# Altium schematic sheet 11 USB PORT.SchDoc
size 420 x 297 mm
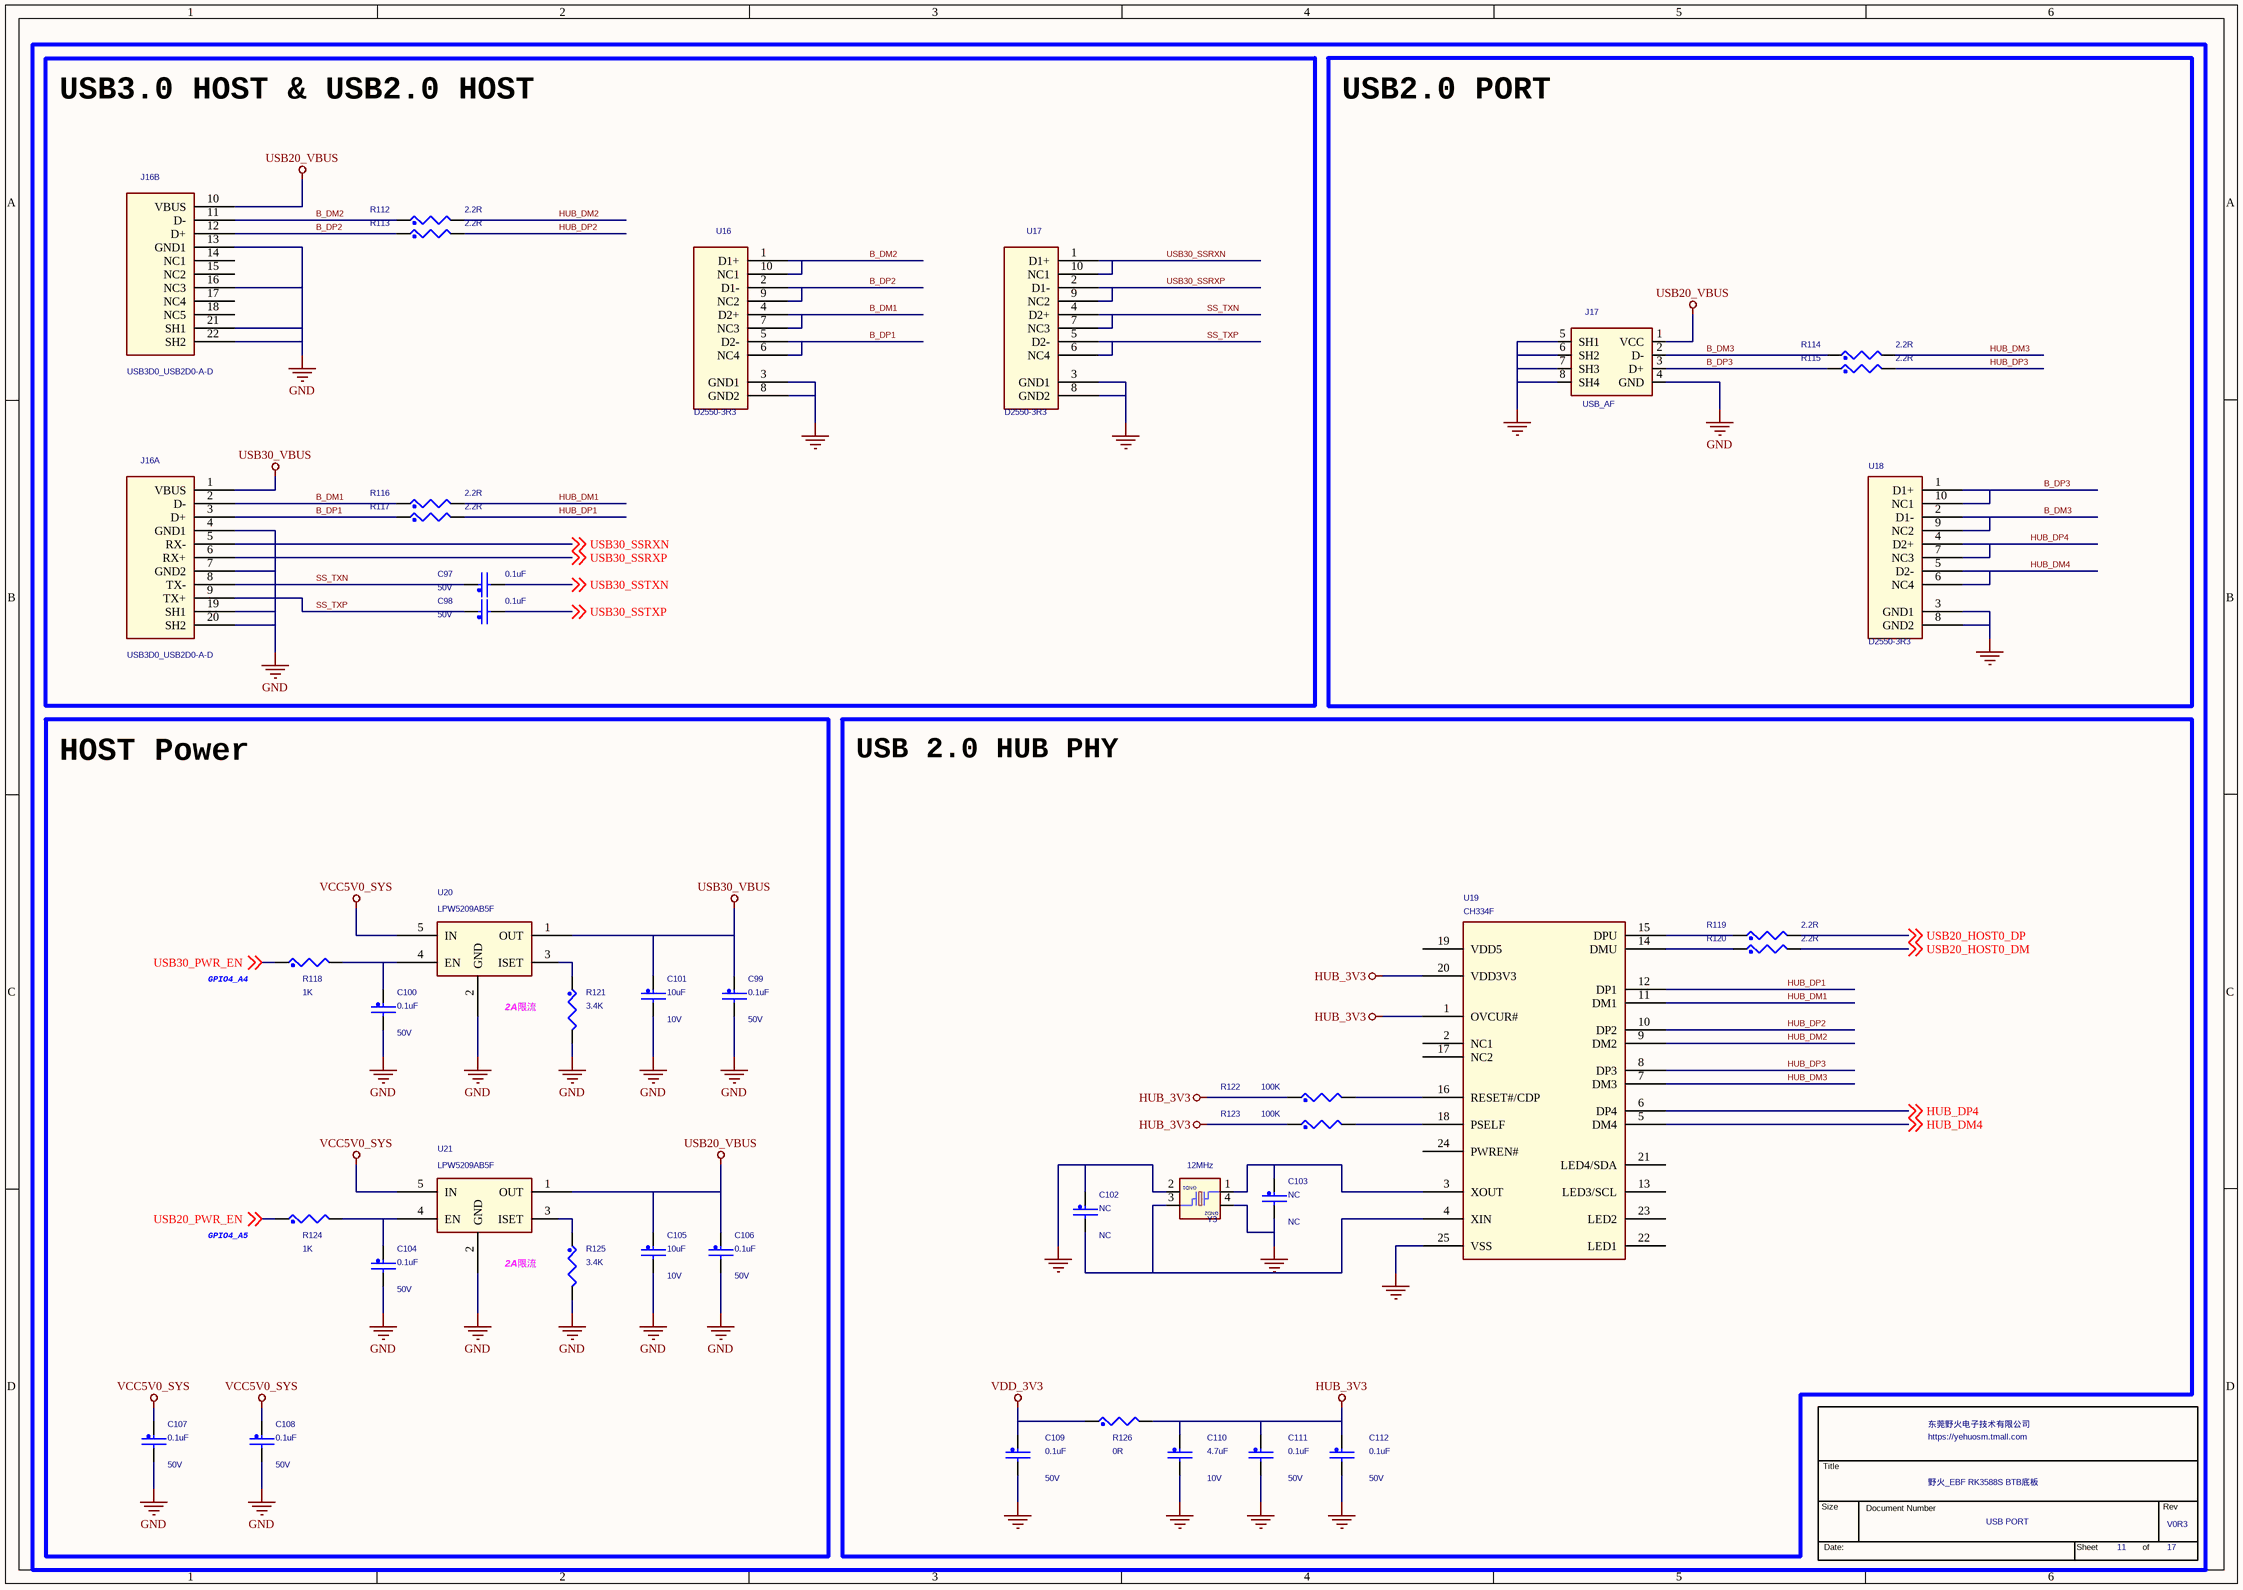
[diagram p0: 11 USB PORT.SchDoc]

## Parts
*  Page Count: 17  Page Number: 11  OrgName: 东莞野火电子技术有限公司  Title: 野火_EBF RK3588S BTB底板  RevCode: V0R3  Doc: USB PORT  (hidden comment: TitleBlock_YHSCH)  (graphical)
C97  0.1uF  Voltage: 50V  [C0402]
C98  0.1uF  Voltage: 50V  [C0402]
C99  0.1uF  Voltage: 50V  [C0402]
C100  0.1uF  Voltage: 50V  [C0402]
C101  10uF  Voltage: 10V  [C0402]
C102  NC  [C0402]
C103  NC  [C0402]
C104  0.1uF  Voltage: 50V  [C0402]
C105  10uF  Voltage: 10V  [C0402]
C106  0.1uF  Voltage: 50V  [C0402]
C107  0.1uF  Voltage: 50V  [C0402]
C108  0.1uF  Voltage: 50V  [C0402]
C109  0.1uF  Voltage: 50V  [C0402]
C110  4.7uF  Voltage: 10V  [C0402]
C111  0.1uF  Voltage: 50V  [C0402]
C112  0.1uF  Voltage: 50V  [C0402]
J16  USB3D0_USB2D0-A-D  [USB3D0-AF-18P]  (parts A,B of 2)
J17  USB_AF  [USB-AF]
R112  2.2R  [R0402]
R113  2.2R  [R0402]
R114  2.2R  [R0402]
R115  2.2R  [R0402]
R116  2.2R  [R0402]
R117  2.2R  [R0402]
R118  1K  [R0402]
R119  2.2R  [R0402]
R120  2.2R  [R0402]
R121  3.4K  [R0402]
R122  100K  [R0402]
R123  100K  [R0402]
R124  1K  [R0402]
R125  3.4K  [R0402]
R126  0R  [R0603]
U16  D2550-3R3  [son10_2r50x1r00x0r50]
U17  D2550-3R3  [son10_2r50x1r00x0r50]
U18  D2550-3R3  [son10_2r50x1r00x0r50]
U19  CH334F  [QFN24]
U20  LPW5209AB5F  [SOT23-5]
U21  LPW5209AB5F  [SOT23-5]
Y3  12MHz  [3225]

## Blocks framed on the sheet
USB3.0 HOST & USB2.0 HOST: C97 C98 J16 R112 R113 R116 R117 U16 U17
USB2.0 PORT: J17 R114 R115 U18
HOST Power: C99-C101 C104-C108 R118 R121 R124 R125 U20 U21
USB 2.0 HUB PHY: C102 C103 C109-C112 R119 R120 R122 R123 R126 U19 Y3

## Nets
GND: C99.2 C100.2 C101.2 C102.1 C103.2 C104.2 C105.2 C106.2 C107.2 C108.2 C109.2 C110.2 C111.2 C112.2 J16.4(GND1) J16.7(GND2) J16.13(GND1) J16.16(NC3) J16.19(SH1) J16.20(SH2) J16.21(SH1) J16.22(SH2) J17.4(GND) J17.5(SH1) J17.6(SH2) J17.7(SH3) J17.8(SH4) R121.2 R125.2 U16.3(GND1) U16.8(GND2) U17.3(GND1) U17.8(GND2) U18.3(GND1) U18.8(GND2) U19.25(VSS) U20.2(GND) U21.2(GND) Y3.2(GND1) Y3.4(GND2)
HUB_3V3: C110.1 C111.1 C112.1 R122.1 R123.1 R126.2 U19.1(OVCUR#) U19.20(VDD3V3)
USB20_VBUS: C105.1 C106.1 J16.10(VBUS) J17.1(VCC) U21.1(OUT)
USB30_VBUS: C99.1 C101.1 J16.1(VBUS) U20.1(OUT)
VCC5V0_SYS: C107.1 C108.1 U20.5(IN) U21.5(IN)
VDD_3V3: C109.1 R126.1
B_DM1: J16.2(D-) R116.1 U16.4(D2+) U16.7(NC3)
B_DM2: J16.11(D-) R112.1 U16.1(D1+) U16.10(NC1)
B_DM3: J17.2(D-) R114.1 U18.2(D1-) U18.9(NC2)
B_DP1: J16.3(D+) R117.1 U16.5(D2-) U16.6(NC4)
B_DP2: J16.12(D+) R113.1 U16.2(D1-) U16.9(NC2)
B_DP3: J17.3(D+) R115.1 U18.1(D1+) U18.10(NC1)
HUB_DM1: R116.2 U19.11(DM1)
HUB_DM2: R112.2 U19.9(DM2)
HUB_DM3: R114.2 U19.7(DM3)
HUB_DM4: U18.5(D2-) U18.6(NC4) U19.5(DM4) ; off-sheet HUB_DM4
HUB_DP1: R117.2 U19.12(DP1)
HUB_DP2: R113.2 U19.10(DP2)
HUB_DP3: R115.2 U19.8(DP3)
HUB_DP4: U18.4(D2+) U18.7(NC3) U19.6(DP4) ; off-sheet HUB_DP4
SS_TXN: C97.1 J16.8(TX-) U17.4(D2+) U17.7(NC3)
SS_TXP: C98.1 J16.9(TX+) U17.5(D2-) U17.6(NC4)
USB20_HOST0_DM: R120.2 ; off-sheet USB20_HOST0_DM
USB20_HOST0_DP: R119.2 ; off-sheet USB20_HOST0_DP
USB20_PWR_EN: R124.1 ; off-sheet USB20_PWR_EN
USB30_PWR_EN: R118.1 ; off-sheet USB30_PWR_EN
USB30_SSRXN: J16.5(RX-) U17.1(D1+) U17.10(NC1) ; off-sheet USB30_SSRXN
USB30_SSRXP: J16.6(RX+) U17.2(D1-) U17.9(NC2) ; off-sheet USB30_SSRXP
USB30_SSTXN: C97.2 ; off-sheet USB30_SSTXN
USB30_SSTXP: C98.2 ; off-sheet USB30_SSTXP
NetC100_1: C100.1 R118.2 U20.4(EN)
NetC102_2: C102.2 U19.4(XIN) Y3.3
NetC103_1: C103.1 U19.3(XOUT) Y3.1
NetC104_1: C104.1 R124.2 U21.4(EN)
NetR119_1: R119.1 U19.15(DPU)
NetR120_1: R120.1 U19.14(DMU)
NetR121_1: R121.1 U20.3(ISET)
NetR122_2: R122.2 U19.16(RESET#/CDP)
NetR123_2: R123.2 U19.18(PSELF)
NetR125_1: R125.1 U21.3(ISET)

Not connected (* = marked no-connect by the designer): J16 14(NC1) 15(NC2) 17(NC4) 18(NC5); U19 2(NC1) 13(LED3/SCL) 17(NC2) 19(VDD5) 21(LED4/SDA) 22(LED1) 23(LED2) 24(PWREN#)

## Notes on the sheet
- (near R118) GPIO4_A4
- (near U20) 2A限流
- (near R124) GPIO4_A5
- (near U21) 2A限流

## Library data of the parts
* = TitleBlock_YHSCH: Cage Code: 1
C97 C100 C104 C107 = CAP_NP: CLASS: DISCRETE; 生命周期: 量产; 价格: 0.029826; 规格书: 风华电容.pdf; 类别: 贴片电容0402; 品牌: 风华; 条码: EBF29060118; 规格编号: 0402X104K500NT; 规格: 贴片电容0.1uF 10% 50V X5R 0402
C98 C99 C106 C108 = CAP_NP: CLASS: DISCRETE; 规格: 贴片电容0.1uF 10% 50V X5R 0402; 规格编号: 0402X104K500NT; 条码: EBF29060118; 品牌: 风华; 类别: 贴片电容0402; 规格书: 风华电容.pdf; 价格: 0.029826; 生命周期: 量产
C101 C105 = CAP_NP: CLASS: DISCRETE; 规格: 贴片电容10uF 20% 10V X5R 0402; 规格编号: CL05A106MP8NUB8; 条码: EBF29060247; 品牌: 三星; 类别: 贴片电容0402; 规格书: 三星电容.pdf; 价格: 0.518415; 生命周期: 量产
C102 = CAP_NP: CLASS: DISCRETE; 类别: 贴片电容0402; 条码: EBF29060149; 规格: 贴片电容NC 预留
C103 = CAP_NP: CLASS: DISCRETE; 规格: 贴片电容NC 预留; 条码: EBF29060149; 类别: 贴片电容0402
C109 C111 C112 = CAP_NP: CLASS: DISCRETE; 规格: 贴片电容0.1uF 10% 50V X5R 0402; 规格编号: 0402X104K500NT; 条码: EBF29060118; 品牌: 风华; 类别: 贴片电容0402; 规格书: 风华电容.pdf; 生命周期: 量产; 价格: 0.029826
C110 = CAP_NP: CLASS: DISCRETE; 规格: 贴片电容4.7uF 10% 10V X5R 0402; 规格编号: CC0402KRX5R6BB475; 条码: EBF29060248; 品牌: 国巨; 类别: 贴片电容0402; 规格书: 国巨-贴片电容.pdf; 价格: 0.059058; 生命周期: 量产
J16 = USB3D0_USB2D0-A-D: 品牌: 富士康; 规格: USB3.0_USB2.0母座; 规格编号: UEA1112C-UHS6-4F; 条码: EBF29040092; 类别: USB接口; 规格书: UEA1112C-UHS6-4F.pdf; 生命周期: 量产
J17 = USB_AF: 生命周期: 量产; 价格: 0.5872; 规格书: 精拓金-USB侧插.pdf; 类别: USB接口; 品牌: 精拓金; 条码: EBF29040024; 规格编号: USB-AF侧插铜; 规格: 垂直 额定电流1.5A 母座 USB - Type A USB 2.0
R112 R115-R117 R119 = RES: CLASS: DISCRETE; 生命周期: 量产; 价格: 0.003072; 规格书: 厚声-无铅厚膜电阻.pdf; 类别: 贴片电阻0402; 品牌: 厚声; 条码: EBF29070280; 规格编号: 0402WGF220KTCE; 规格: 贴片电阻2.2R 1% 1/16W 0402
R113 R114 R120 = RES: CLASS: DISCRETE; 规格: 贴片电阻2.2R 1% 1/16W 0402; 规格编号: 0402WGF220KTCE; 条码: EBF29070280; 品牌: 厚声; 类别: 贴片电阻0402; 规格书: 厚声-无铅厚膜电阻.pdf; 价格: 0.003072; 生命周期: 量产
R118 R124 = RES: CLASS: DISCRETE; 生命周期: 量产; 规格书: 合科泰-RI系列电阻.pdf; 类别: 贴片电阻0402; 品牌: 合科泰; 条码: EBF29070050; 规格编号: RI0402L1001FT; 规格: 贴片电阻1K 1% 1/16W 0402
R121 = RES: CLASS: DISCRETE; 生命周期: 量产; 规格书: 合科泰-RI系列电阻.pdf; 类别: 贴片电阻0402; 品牌: 合科泰; 条码: EBF29070186; 规格编号: RI0402L3401FT; 规格: 贴片电阻3.4K 1% 1/16W 0402
R122 = RES: CLASS: DISCRETE; 生命周期: 量产; 规格书: 合科泰-RI系列电阻.pdf; 类别: 贴片电阻0402; 品牌: 合科泰; 条码: EBF29070054; 规格编号: RI0402L1003FT; 规格: 贴片电阻100K 1% 1/16W 0402
R123 = RES: CLASS: DISCRETE; 规格: 贴片电阻100K 1% 1/16W 0402; 规格编号: RI0402L1003FT; 条码: EBF29070054; 品牌: 合科泰; 类别: 贴片电阻0402; 规格书: 合科泰-RI系列电阻.pdf; 生命周期: 量产
R125 = RES: CLASS: DISCRETE; 规格: 贴片电阻3.4K 1% 1/16W 0402; 规格编号: RI0402L3401FT; 条码: EBF29070186; 品牌: 合科泰; 类别: 贴片电阻0402; 规格书: 合科泰-RI系列电阻.pdf; 生命周期: 量产
R126 = RES: CLASS: DISCRETE; 生命周期: 量产; 规格书: 合科泰-RI系列电阻.pdf; 类别: 贴片电阻0603; 品牌: 合科泰; 条码: EBF29070063; 规格编号: RI0603L0000FT; 规格: 贴片电阻0R 1% 1/10W 0603
U16 = RCLAMP0524P: 丝印: 3324P; 备注: 猫5 HDMI2.1新物料; 规格: 用于 USB3.0、HDMI2.1和高速接口的四路0.13pF、3.3V、±12kV ESD 保护二极管; 条码: EBFCIS231110170954; 品牌: 千虹; 类别: 贴片四路ESD; 规格书: 千虹_D2550-3R3.pdf; 生命周期: 量产
U17 U18 = RCLAMP0524P: 丝印: 3324P; 备注: 猫5 HDMI2.1新物料; 生命周期: 量产; 规格书: 千虹_D2550-3R3.pdf; 类别: 贴片四路ESD; 品牌: 千虹; 条码: EBFCIS231110170954; 规格: 用于 USB3.0、HDMI2.1和高速接口的四路0.13pF、3.3V、±12kV ESD 保护二极管
U19 = CH334F: 生命周期: 量产; 价格: 2.09; 规格书: 南京沁恒_CH334F.pdf; 类别: USB芯片; 品牌: 南京沁恒; 条码: EBFCIS221222095807; 规格: USB HUB芯片 工作电压3.3V 5V 协议类别USB2.0 支持高速(480Mbps) 全速(12Mbps)和低速(1.5Mbps)模式
U20 U21 = LPW5209AB5F: 规格: 集成电源开关 导通电阻：80mΩ 最大可设置保护电流：2.1A 输入电压：2.5V~6V 静态电流：30uA 其他功能：软启动、短路保护、热保护; 条码: EBF29280015; 品牌: 微源半导体; 类别: 功率开关; 规格书: 微源半导体_LPW5209AB5F.pdf; 价格: 0.468063; 生命周期: 量产
Y3 = CRYSTAL_4P: CLASS: IC; 可替代料: EBF29100013; 生命周期: 量产; 价格: 0.327763; 规格书: 扬兴科技-贴片晶振.pdf; 类别: 贴片晶振 3225; 品牌: 扬兴科技; 规格编号: X322512MSB4SI; 规格: 无源晶振12MHz ±10ppm 80Ω 20pF -40℃~+85℃ 3225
